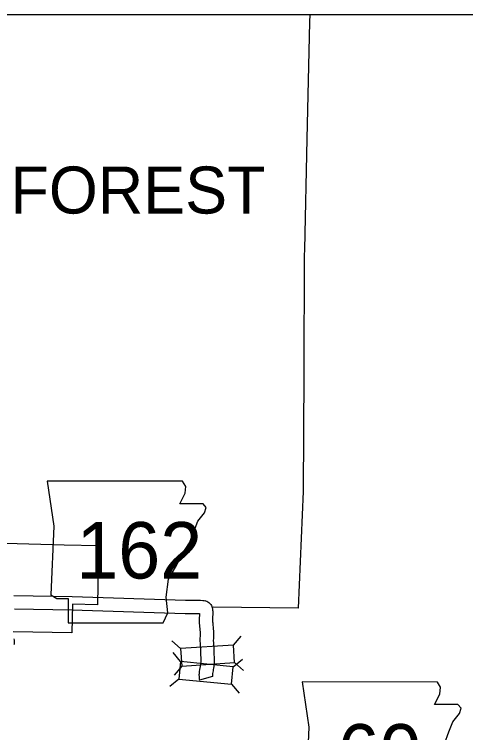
# Model space of a CAD drawing. Extents: x 535214 to 694517, y 381272 to 484355.
# Drawn here: x 547357 to 552423, y 472159 to 480223 of the extents above; entities that cross this region are included whole.
import ezdxf

# ---------------------------------------------------------------- set-up
doc = ezdxf.new("R2010")
doc.units = 0
for name, color, linetype in [('1', 7, 'Continuous'), ('Level 10', 7, 'Continuous'), ('Level 20', 7, 'Continuous'), ('Level 21', 7, 'Continuous'), ('Level 6', 7, 'Continuous'), ('Level 8', 7, 'Continuous')]:
    doc.layers.add(name, color=color, linetype=linetype)

msp = doc.modelspace()

# ---------------------------------------------------------------- linework, layer by layer
at = {"layer": '1'}
msp.add_lwpolyline([(535213.7, 480223.3), (566227, 480223.3), (566227, 448175.2), (535213.7, 448175.2)], close=True, dxfattribs=at)
at = {"layer": 'Level 10'}
msp.add_line((549581.3, 472788), (549437.2, 472746.5), dxfattribs=at)
for points in [[(547351.6, 473699.2), (548005.3, 473686.3), (549279.6, 473646.9), (549447.7, 473644.9), (549472.7, 473643.9), (549482.1, 473643.1), (549490.7, 473641.8)], [(549495.5, 473640.9), (549504.8, 473638.9), (549517.5, 473634.2), (549529.9, 473627.7), (549539.3, 473620.7), (549548, 473613.5), (549555.3, 473605.5), (549561.7, 473597.5), (549570.1, 473585.7), (549574.6, 473575), (549578.7, 473564.6), (549582.1, 473546.8), (549582.3, 473536.2), (549582.8, 473533.1), (549584.4, 473523.1), (549583.2, 473423.5), (549582.9, 473401.4), (549583.4, 473392.2), (549584.2, 473377.8), (549586, 473362.5), (549587.8, 473345.8), (549589.3, 473332.7), (549590.6, 473318.8), (549591.5, 473302.3), (549591.5, 473285.2), (549591.6, 473261.7), (549591.7, 473238.5), (549591, 473218.1), (549590.7, 473188.1), (549591.7, 473170.2), (549592.9, 473149.2), (549595.2, 473118.7), (549596.5, 473050.6), (549599.1, 472990.7), (549599.9, 472971.3), (549599.8, 472955.7), (549598.9, 472939.1), (549597.8, 472921.7), (549595.5, 472901.7), (549592.9, 472882.9), (549590.2, 472867.3), (549587.3, 472853.6), (549584.1, 472838.5), (549581.5, 472823.6), (549580.6, 472816.3), (549580.2, 472811.1), (549580, 472805.8), (549580.3, 472797.7), (549580.7, 472792.3), (549581.1, 472788.8), (549581.2, 472788.6), (549581.3, 472788)], [(547357.1, 473549.1), (548001.5, 473536.3), (549276.4, 473497), (549434, 473495.1)], [(549434, 473495.1), (549433.2, 473425.6), (549432.8, 473398.3), (549433.6, 473383.5), (549434.8, 473364.5), (549437, 473345.9), (549438.7, 473329.7), (549440.1, 473316.9), (549441, 473307.3), (549441.5, 473298.4), (549441.5, 473285), (549441.6, 473261.1), (549441.7, 473240.9), (549441, 473221.3), (549440.7, 473184.9), (549441.9, 473161.9), (549443.3, 473139), (549445.3, 473111.7), (549446.6, 473046), (549449.2, 472984.1), (549449.9, 472968.5), (549449.9, 472960.2), (549449.2, 472948.3), (549448.3, 472935.2), (549446.6, 472920.2), (549444.7, 472906), (549442.9, 472895.6), (549440.6, 472884.7), (549436.8, 472867.3), (549433, 472845.6), (549431.3, 472831), (549430.4, 472819.6), (549429.9, 472806), (549430.5, 472789.6), (549431.3, 472777.5), (549433.2, 472763), (549435.8, 472751.4), (549437.2, 472746.5)], [(547356.1, 473149.4), (547357.5, 473156.8), (547358.8, 473165.8), (547360, 473184.7), (547358.7, 473191.7), (547358.2, 473198.2), (547356.1, 473210.7)]]:
    msp.add_lwpolyline(points, dxfattribs=at)
at = {"layer": 'Level 20'}
for p, q in [((549816.5, 473142.4), (549903.4, 473241.8)), ((549223.8, 473102.4), (549124.4, 473189.3)), ((549223.5, 472956.9), (549139.6, 473058.8)), ((549814.7, 472899.5), (549916.6, 472983.4)), ((549237.2, 472904.9), (549150.3, 472805.5)), ((549829.8, 472944.8), (549929.2, 472857.9)), ((549204.3, 472759.8), (549102.4, 472675.9)), ((549795.6, 472702.4), (549879.4, 472600.5))]:
    msp.add_line(p, q, dxfattribs=at)
for points in [[(549816.5, 473142.4), (549223.8, 473102.4), (549237.2, 472904.9), (549829.8, 472944.8)], [(549814.7, 472899.5), (549223.5, 472956.9), (549204.3, 472759.8), (549795.6, 472702.4)]]:
    msp.add_lwpolyline(points, close=True, dxfattribs=at)
at = {"layer": 'Level 21'}
for points in [[(547725.2, 474982.9), (547801.3, 474475.4), (547767.5, 473705.6), (547835.1, 473663.3), (547962, 473663.3), (547962, 473392.6), (549027.9, 473392.6), (549078.6, 473502.6), (549061.7, 473680.2), (549087.1, 473883.2), (549180.1, 474044), (549239.3, 474162.4), (549323.9, 474289.3), (549374.7, 474424.6), (549417, 474534.6), (549493.1, 474627.6), (549510, 474686.8), (549476.2, 474729.1), (549214, 474729.1), (549273.2, 474847.6), (549281.6, 474923.7), (549246.5, 474982.2)], [(550586.2, 472727.8), (550662.3, 472220.3), (550628.5, 471450.5), (550696.2, 471408.2), (550823.1, 471408.2), (550823.1, 471137.6), (551888.9, 471137.6), (551939.6, 471247.5), (551922.7, 471425.2), (551948.1, 471628.2), (552041.1, 471788.9), (552100.4, 471907.3), (552184.9, 472034.2), (552235.7, 472169.5), (552278, 472279.5), (552354.1, 472372.6), (552371, 472431.8), (552337.2, 472474.1), (552075, 472474.1), (552134.2, 472592.5), (552142.6, 472668.6), (552107.6, 472727.1)]]:
    msp.add_lwpolyline(points, close=True, dxfattribs=at)
at = {"layer": 'Level 6'}
for points in [[(547258.2, 474286.1), (547918.1, 474269)], [(547918.1, 474269), (548301.6, 474260.5)], [(548301.6, 474260.5), (548290.9, 473594.5)], [(548010.8, 473603), (548003.3, 473277.9), (547343.5, 473291)], [(548290.9, 473594.5), (548010.8, 473603)]]:
    msp.add_lwpolyline(points, dxfattribs=at)
at = {"layer": 'Level 8'}
for points in [[(550672.5, 480223.3), (550669.4, 480137.2), (550638.8, 478825.1), (550615.6, 477584.6)], [(550615.6, 477584.6), (550609.1, 477516.1), (550607.3, 476190.6), (550598, 474865.9), (550542.3, 473558.2)], [(550542.3, 473558.2), (549589.2, 473568.7)]]:
    msp.add_lwpolyline(points, dxfattribs=at)

# ---------------------------------------------------------------- texts
at = {"layer": 'Level 21'}
for s, p in [('162', (548052.3, 473889.3)), ('60', (550985.2, 471620.5))]:
    msp.add_text(s, height=633.6, dxfattribs=at).set_placement(p)
at = {"layer": 'Level 8'}
msp.add_text('FOREST', height=528, dxfattribs=at).set_placement((547313.5, 477987))

doc.saveas('drawing.dxf')
